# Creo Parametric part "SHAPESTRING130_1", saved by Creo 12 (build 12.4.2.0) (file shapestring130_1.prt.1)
Units: Custom; MM, KILOGRAM, SECS

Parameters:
  PTC_WM_ITERATION = "0"
  PTC_WM_VERSION = "-.0"
  PTC_WM_LIFECYCLE_STATE = "In Work"
  PTC_WM_LIFECYCLE = "MO_CADDocument"
  PTC_WM_CREATED_BY = "Maximilian Roepper (Z0017RMS: MO)"
  PTC_WM_CREATED_ON = "18-Sep-26 11:36:42 AM"
  PTC_WM_MODIFIED_BY = "Maximilian Roepper (Z0017RMS: MO)"
  PTC_WM_MODIFIED_ON = "18-Sep-26 11:36:46 AM"
  PDMLINKNUMBER = "PDM000071454892"
  PTC_WM_NAME = "shapestring130_1.prt"
  PTC_WM_NUMBER = "PDM000071454892"

Other parameters: WEIGHT, WEIGHT_FACTOR, WEIGHT_ADD, _MASS_TEMP, _DIFF_TEMP, MC_ERRORS, SUPPLIER

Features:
  1. coordinate system
  2. datum plane "PRT_YZ"
  3. datum plane "PRT_XY"
  4. datum plane "PRT_XZ"
  5. coordinate system
  6. datum axis
  7. datum axis
  8. datum axis
  9. coordinate system
  10. imported feature

Other named items: PRT, SIEMENS_MO, DRW_VIEW_ORG, PRT_X, PRT_Y, PRT_Z, CS0, ROUGH_GROB

Layers: 00_STD_CSYS-KSYS, 01_STD_PLANES-EBENEN, 02_STD_AXES-ACHSEN, 03_STD_CSYS-KSYS, 24_IMPORT_FEAT-IMPORT_KE, INTFCLR

Surfaces: 1 plane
